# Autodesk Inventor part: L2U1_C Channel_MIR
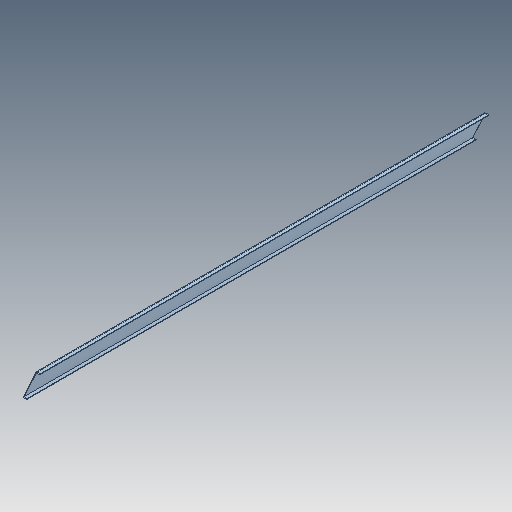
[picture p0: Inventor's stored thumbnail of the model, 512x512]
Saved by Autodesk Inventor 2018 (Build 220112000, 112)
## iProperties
Created: 2018-02
Part Number: L2U1_C Channel_MIR
Material: Steel, Mild
Document SubType Name: Modeling
Designer: STK
Density: 7.85 g/cm^3
Appearance: Semi-Polished
Author: STK
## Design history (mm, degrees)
derived "L2U1_C Channel.ipt"
  sketch "Sketch1"
    geometry: L1 (-12.7, 177.8)-(-12.7, -177.8) reference; L2 (0, -190.5)-(0, 190.5) reference; L3 (0, -190.5)-(-92.075, -190.5) reference; L4 (-92.075, -190.5)-(-92.075, -177.8) reference; L5 (-92.075, -177.8)-(-12.7, -177.8) reference; L6 (0, 190.5)-(-92.075, 190.5) reference; L7 (-92.075, 190.5)-(-92.075, 177.8) reference; L8 (-92.075, 177.8)-(-12.7, 177.8) reference; L9 (0, 0)-(-92.075, 0) reference
  sketch "Sketch2"
    geometry: L1 (6273.832, 5940.973)-(11379.2, 0) reference; L2 (11379.2, 381)-(0, 381) reference; L3 (11379.2, 0)-(11379.2, 381) reference; L4 (11379.2, 0)-(11051.788, 381) reference; L5 (11379.2, 381)-(11051.788, 381) reference; L6 (11379.2, 381)-(0, 381) reference; L7 (11379.2, 381)-(11379.2, 0) reference; L8 (11379.2, 368.3)-(0, 368.3) reference; L9 (-83.322, 477.96)-(5022.046, -5463.013) reference; L10 (0, 0)-(11379.2, 0) reference; L11 (0, 0)-(327.412, 0) reference; L12 (0, 368.3)-(0, 381) reference; L13 (0, 381)-(327.412, 0) reference; L14 (0, 0)-(0, 381) reference; 1 further point
  sketch "Sketch3"
    geometry: L1 (-83.322, 477.96)-(5022.046, -5463.013) reference; L2 (0, 381)-(0, 0) reference; L3 (0, 0)-(11379.2, 0) reference; L4 (11051.788, 381)-(0, 381) reference; L5 (0, 381)-(0, 0) reference; L6 (11379.2, 0)-(0, 0) reference; L7 (327.412, 0)-(0, 381) reference; 1 further point
feature "Solid1::L2U1_C Channel.ipt"
tag "TaggingFeature1"
body "Solid1"
